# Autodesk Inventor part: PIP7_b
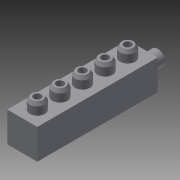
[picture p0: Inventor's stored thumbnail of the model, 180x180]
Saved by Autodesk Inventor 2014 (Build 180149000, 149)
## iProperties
Shininess: 64.0
Length Units: 11272
Angle Units: 11279
Time Units: 11290
Mass Units: 11286
Length Display Precision: 3
Angle Display Precision: 2
Compacted: True
Part Number: PIP7_b
Document SubType Name: Modeling
Created: 2003-01
Designer: qauser
Density: 1 g/cm^3
Mass: 565.139 g
Surface Area: 600.437 cm^2
Volume: 565.139 cm^3
Material: Generic
Appearance: Default
Density: 0.0
Volumn: 0.0
Area: 0.0
PropertySet Name: Model Information
Control State: 0
Master: False
Checked Out: False
Author: qauser
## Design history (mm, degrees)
sketch "Sketch1"
  geometry: L1 (0, 0)-(50.8, 0); L2 (50.8, 0)-(50.8, 50.8); L3 (50.8, 50.8)-(0, 50.8); L4 (0, 50.8)-(0, 0)
  constraints: 8 end point, 2 parallel, 1 horizontal, 1 perpendicular
  dimensions: "d0" = 50.8 distance between parallel lines of L2 L4 (= d1); "d1" = 50.8 distance between parallel lines of L1 L3
extrude "Extrusion1" new body sketch "Sketch1" distance "d2" = 203.2; taper "d3" = 0 deg
workplane "Work Plane1"
sketch "Sketch2"
  geometry: L1 (0, 50.8)-(50.8, 50.8) reference; L2 (25.4, 50.8)-(25.4, 69.85); L3 (31.75, 50.8)-(31.75, 69.85); L4 (31.75, 69.85)-(34.913, 69.85); L5 (34.913, 69.85)-(38.1, 64.206); L6 (38.1, 64.206)-(38.1, 50.8)
  constraints: 10 end point, 2 parallel, 2 perpendicular, 2 point on line, 1 midpoint
  dimensions: "d5" = 19.05 distance of L2.start L2.end; "d11" = 12.7 diameter of L3 L2; "d12" = 25.4 diameter of L6 L2; "d25" = 19.05 distance of L3.start L3.end (= d5)
revolve "Revolution1" sketch "Sketch2" stored, may be unused: angle "d13" = 90 deg
pattern_linear "Rectangular Pattern1" dims "d16" = 38.1 (= 0.5 x d4 + 0.25 x d2)
sketch "Sketch3"
  geometry: L1 (0, 50.8)-(0, 0) reference; L2 (-50.8, 50.8)-(0, 50.8) reference; C1 r 12.7 at (-25.4, 25.4)
  constraints: 1 centre point
  dimensions: "d17" = 25.4 diameter of C1; "d26" = 25.4 distance from line of L2 C1.centre (= 0.5 x d1); "d27" = 25.4 distance from line of L1 C1.centre (= d26)
extrude "Extrusion2" join sketch "Sketch3" distance "d20" = 25.4; taper "d21" = 0 deg
sketch "Sketch4"
  geometry: C1 r 12.7 at (0, 0) reference; C2 r 7.938 at (0, 0)
  constraints: 1 centre point, 1 coincident, 1 concentric
  dimensions: "d22" = 15.875 diameter of C2
extrude "Extrusion3" cut sketch "Sketch4" distance "d23" = 25.4; taper "d24" = 0 deg
body "Solid1"
other parameters: "d4" = -25.4
